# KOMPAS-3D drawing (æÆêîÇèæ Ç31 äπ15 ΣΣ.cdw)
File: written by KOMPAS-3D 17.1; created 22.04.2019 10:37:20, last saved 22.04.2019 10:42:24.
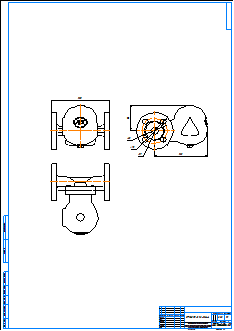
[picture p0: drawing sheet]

Sheet 1: A1, portrait

Title block, sheet 1: name: СТИМАКС А31 Ду15 фф; material: Внимание! Данный продукт является объектом авторского права ООО «Торговый Дом АДЛ». / Запрещается изменение, копирование, распространение / (в том числе путем копирования на другие сайты и ресурсы в Интернете) / или любое иное использование информации и объектов без предварительного / согласия правообладателя (ООО «Торговый Дом АДЛ»).; mass: 6,56; sheets: 1; organisation: ООО "Торговый дом АДЛ"; sheet format: A1

Views: Вид 1, Проекционный вид 2, Проекционный вид 3
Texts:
  user
Dimensions and other numbers on the sheet: 135; 150; 65; 66; 19; 95; 1:1; 1; 6,56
